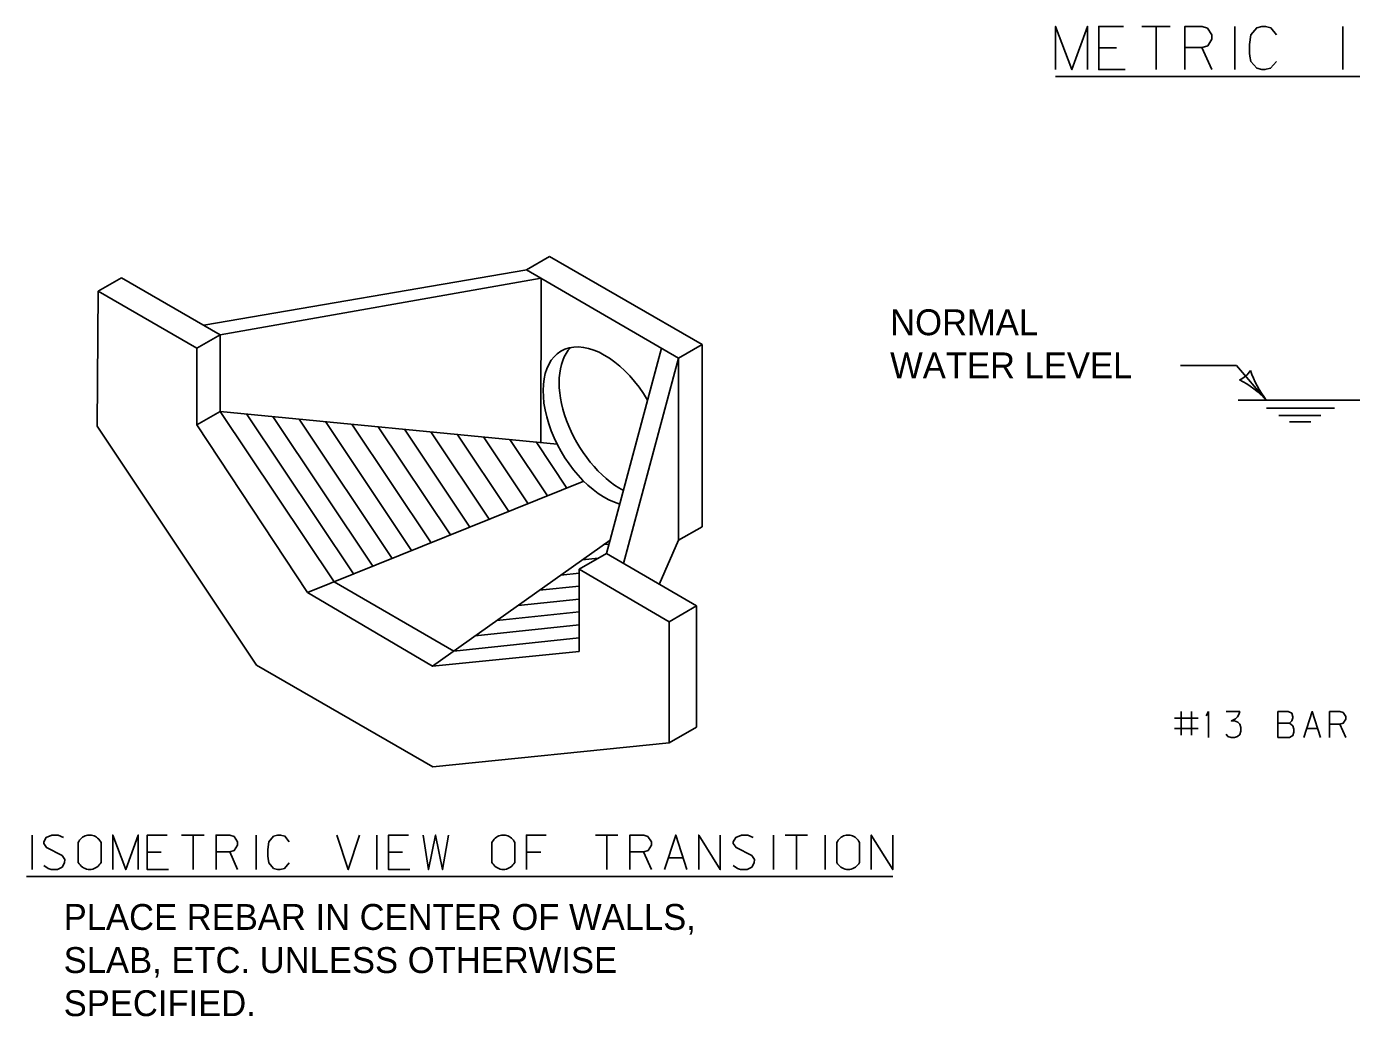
# Model space of a CAD drawing. Extents: x 49991.4 to 50043, y 49987.6 to 50011.4.
# Drawn here: x 50035.187 to 50038.261, y 49996.433 to 49998.729 of the extents above; entities that cross this region are included whole.
import ezdxf

# ---------------------------------------------------------------- set-up
doc = ezdxf.new("R2010")
doc.units = 0
for name, color, linetype in [('Level 1', 7, 'Continuous'), ('Level 2', 7, 'Continuous'), ('Level 3', 7, 'Continuous')]:
    doc.layers.add(name, color=color, linetype=linetype)

msp = doc.modelspace()

# ---------------------------------------------------------------- linework, layer by layer
at = {"layer": 'Level 1'}
for p, q in [((50036.4004, 49998.1956), (50036.3472, 49998.1648)), ((50036.7543, 49997.9911), (50036.4004, 49998.1956)), ((50036.3473, 49998.1648), (50035.5983, 49998.0359)), ((50036.3472, 49998.1648), (50036.6998, 49997.9596)), ((50035.3528, 49998.1146), (50035.4073, 49998.1461)), ((50035.6363, 49998.0139), (50035.4073, 49998.1461)), ((50036.3811, 49998.1451), (50035.6363, 49998.0139)), ((50036.3811, 49998.1451), (50036.3798, 49997.7642)), ((50035.3528, 49998.1146), (50035.3507, 49997.8017)), ((50035.5818, 49997.9824), (50035.3528, 49998.1146)), ((50035.5818, 49997.9824), (50035.6363, 49998.0139)), ((50035.6363, 49998.0139), (50035.6363, 49997.8361)), ((50035.5818, 49997.9824), (50035.5818, 49997.8046)), ((50036.5323, 49997.5066), (50036.6601, 49997.9827)), ((50036.6998, 49997.9596), (50036.7543, 49997.9911)), ((50036.7543, 49997.9911), (50036.7543, 49997.5687)), ((50036.5722, 49997.4834), (50036.6998, 49997.9596)), ((50036.6998, 49997.5372), (50036.6998, 49997.9596)), ((50037.9983, 49997.8625), (50038.3287, 49997.8625)), ((50035.5818, 49997.8046), (50035.6363, 49997.8361)), ((50035.6363, 49997.8361), (50035.9002, 49997.4411)), ((50035.6363, 49997.8361), (50036.4179, 49997.7605)), ((50035.6974, 49997.8302), (50035.9452, 49997.4592)), ((50035.7585, 49997.8243), (50035.9903, 49997.4773)), ((50035.8195, 49997.8184), (50036.0353, 49997.4954)), ((50038.0635, 49997.8436), (50038.2214, 49997.8436)), ((50038.0927, 49997.8265), (50038.1897, 49997.8265)), ((50035.3507, 49997.8017), (50035.7207, 49997.248)), ((50035.5818, 49997.8046), (50035.8388, 49997.4164)), ((50035.8806, 49997.8125), (50036.0803, 49997.5135)), ((50035.9416, 49997.8066), (50036.1253, 49997.5316)), ((50036.0027, 49997.8007), (50036.1704, 49997.5497)), ((50036.0638, 49997.7948), (50036.2154, 49997.5678)), ((50036.1248, 49997.7889), (50036.2604, 49997.5859)), ((50036.1859, 49997.783), (50036.3055, 49997.604)), ((50038.1176, 49997.8123), (50038.1671, 49997.8123)), ((50036.2469, 49997.7771), (50036.3505, 49997.622)), ((50036.308, 49997.7712), (50036.3955, 49997.6401)), ((50036.3691, 49997.7652), (50036.4405, 49997.6582)), ((50035.8388, 49997.4164), (50036.48, 49997.6741)), ((50036.7543, 49997.5687), (50036.6998, 49997.5372)), ((50036.1288, 49997.2452), (50036.5407, 49997.5378)), ((50036.6998, 49997.5372), (50036.655, 49997.4351)), ((50036.5323, 49997.5066), (50036.4693, 49997.4702)), ((50036.5382, 49997.5285), (50036.5257, 49997.5271)), ((50036.5323, 49997.5066), (50036.7411, 49997.3849)), ((50036.5137, 49997.4958), (50036.4761, 49997.4919)), ((50036.4693, 49997.4611), (50036.4265, 49997.4567)), ((50036.4693, 49997.4702), (50036.4693, 49997.2791)), ((50036.4693, 49997.4702), (50036.6775, 49997.3483)), ((50035.8388, 49997.4164), (50036.1288, 49997.2452)), ((50035.9002, 49997.4411), (50036.1784, 49997.2805)), ((50036.4693, 49997.4311), (50036.3769, 49997.4214)), ((50036.4693, 49997.401), (50036.3273, 49997.3862)), ((50036.7411, 49997.3849), (50036.6775, 49997.3483)), ((50036.7411, 49997.3849), (50036.7411, 49997.1042)), ((50036.4693, 49997.371), (50036.2777, 49997.3509)), ((50036.4693, 49997.3409), (50036.228, 49997.3157)), ((50036.6775, 49997.3483), (50036.6775, 49997.0674)), ((50036.4693, 49997.3108), (50036.1784, 49997.2805)), ((50036.4693, 49997.2791), (50036.1288, 49997.2452)), ((50036.1295, 49997.012), (50035.7207, 49997.248)), ((50036.7411, 49997.1042), (50036.6775, 49997.0674)), ((50036.6775, 49997.0674), (50036.1295, 49997.012))]:
    msp.add_line(p, q, dxfattribs=at)
for centre, start_param, end_param in [((50036.5283, 49997.8013), 4.726836, 8.88612), ((50036.5654, 49997.8211), 0.161802, 2.399384)]:
    msp.add_ellipse(centre, major_axis=(-0.101, 0.1749), ratio=0.57735, start_param=start_param, end_param=end_param, dxfattribs=at)
at = {"layer": 'Level 2'}
for p, q in [((50037.7746, 49998.7287), (50037.84, 49998.7287)), ((50037.8077, 49998.7287), (50037.8077, 49998.6287)), ((50037.9907, 49998.6287), (50037.9907, 49998.7287)), ((50038.2407, 49998.6287), (50038.2407, 49998.7287)), ((50037.7155, 49998.6791), (50037.6746, 49998.6791)), ((50037.9368, 49998.6287), (50037.914, 49998.6798)), ((50037.5746, 49998.6127), (50040.7368, 49998.6127)), ((50037.8656, 49997.1402), (50037.8656, 49997.0852)), ((50037.8899, 49997.1402), (50037.8899, 49997.0852)), ((50037.9296, 49997.1402), (50037.9237, 49997.1298)), ((50037.9296, 49997.1402), (50037.9296, 49997.0802)), ((50037.8502, 49997.1249), (50037.9053, 49997.1249)), ((50038.2476, 49997.0802), (50038.2339, 49997.1109)), ((50037.8502, 49997.1005), (50037.9053, 49997.1005)), ((50038.1569, 49997.1005), (50038.1828, 49997.1005)), ((50035.1996, 49996.7738), (50035.1996, 49996.8538)), ((50035.3067, 49996.8361), (50035.3067, 49996.7901)), ((50035.33, 49996.8538), (50035.3363, 49996.8538)), ((50035.3596, 49996.8361), (50035.3596, 49996.7901)), ((50035.5467, 49996.8538), (50035.599, 49996.8538)), ((50035.5731, 49996.8538), (50035.5731, 49996.7738)), ((50035.7196, 49996.7738), (50035.7196, 49996.8538)), ((50035.9996, 49996.7738), (50035.9996, 49996.8538)), ((50036.2667, 49996.8361), (50036.2667, 49996.7901)), ((50036.29, 49996.8538), (50036.2963, 49996.8538)), ((50036.3196, 49996.8361), (50036.3196, 49996.7901)), ((50036.5067, 49996.8538), (50036.559, 49996.8538)), ((50036.5331, 49996.8538), (50036.5331, 49996.7738)), ((50036.9196, 49996.7738), (50036.9196, 49996.8538)), ((50036.9467, 49996.8538), (50036.999, 49996.8538)), ((50036.9731, 49996.8538), (50036.9731, 49996.7738)), ((50037.0396, 49996.7738), (50037.0396, 49996.8538)), ((50037.0667, 49996.8361), (50037.0667, 49996.7901)), ((50037.09, 49996.8538), (50037.0963, 49996.8538)), ((50037.1196, 49996.8361), (50037.1196, 49996.7901)), ((50035.4994, 49996.8141), (50035.4667, 49996.8141)), ((50035.6765, 49996.7738), (50035.6582, 49996.8147)), ((50036.0594, 49996.8141), (50036.0267, 49996.8141)), ((50036.3473, 49996.8141), (50036.3801, 49996.8141)), ((50036.6365, 49996.7738), (50036.6182, 49996.8147)), ((50036.6755, 49996.8009), (50036.7102, 49996.8009)), ((50035.33, 49996.7738), (50035.3363, 49996.7738)), ((50036.29, 49996.7738), (50036.2963, 49996.7738)), ((50037.09, 49996.7738), (50037.0963, 49996.7738)), ((50035.1867, 49996.7578), (50037.1965, 49996.7578))]:
    msp.add_line(p, q, dxfattribs=at)
for points in [[(50037.5746, 49998.6287), (50037.5746, 49998.7287), (50037.6124, 49998.6287), (50037.6486, 49998.7287), (50037.6486, 49998.6287)], [(50037.7321, 49998.7287), (50037.6746, 49998.7287), (50037.6746, 49998.6287), (50037.736, 49998.6287)], [(50037.8746, 49998.6287), (50037.8746, 49998.7287), (50037.9148, 49998.7287), (50037.9266, 49998.7247), (50037.9368, 49998.709), (50037.9368, 49998.6995), (50037.9274, 49998.6838), (50037.9148, 49998.6798), (50037.8746, 49998.6798)], [(50038.0868, 49998.709), (50038.0742, 49998.7255), (50038.0616, 49998.7287), (50038.053, 49998.7287), (50038.0411, 49998.7255), (50038.0278, 49998.709), (50038.0246, 49998.6869), (50038.0246, 49998.6751), (50038.0246, 49998.6672), (50038.0254, 49998.6602), (50038.0278, 49998.6476), (50038.0411, 49998.6318), (50038.053, 49998.6287), (50038.06, 49998.6287), (50038.0734, 49998.6318), (50038.0868, 49998.6476)], [(50037.9702, 49997.1402), (50038.0019, 49997.1402), (50038, 49997.1331), (50037.9967, 49997.1279), (50037.992, 49997.1232), (50037.9825, 49997.1185), (50037.9896, 49997.1185), (50037.9972, 49997.1152), (50038.0019, 49997.1105), (50038.0043, 49997.1029), (50038.0043, 49997.0949), (50038.0019, 49997.0868), (50037.9967, 49997.0821), (50037.9896, 49997.0802), (50037.9816, 49997.0802), (50037.9745, 49997.0821), (50037.9702, 49997.0873)], [(50038.1172, 49997.1128), (50038.1224, 49997.1185), (50038.1247, 49997.1256), (50038.1247, 49997.1279), (50038.1224, 49997.136), (50038.1143, 49997.1402), (50038.0902, 49997.1402), (50038.0902, 49997.0802), (50038.1172, 49997.0802), (50038.1247, 49997.0845), (50038.1276, 49997.0925), (50038.1276, 49997.0996), (50038.1247, 49997.1067), (50038.1172, 49997.1128), (50038.0902, 49997.1128)], [(50038.1502, 49997.0802), (50038.1701, 49997.1402), (50038.1895, 49997.0802)], [(50038.2102, 49997.0802), (50038.2102, 49997.1402), (50038.2343, 49997.1402), (50038.2414, 49997.1379), (50038.2476, 49997.1284), (50038.2476, 49997.1227), (50038.2419, 49997.1133), (50038.2343, 49997.1109), (50038.2102, 49997.1109)], [(50035.2727, 49996.8481), (50035.2601, 49996.8538), (50035.2456, 49996.8538), (50035.2324, 49996.8481), (50035.2267, 49996.838), (50035.2267, 49996.8342), (50035.233, 49996.8248), (50035.2695, 49996.8059), (50035.2758, 49996.7971), (50035.2752, 49996.7895), (50035.2695, 49996.7794), (50035.2588, 49996.7738), (50035.2437, 49996.7738), (50035.2368, 49996.7763), (50035.2267, 49996.7832)], [(50035.3067, 49996.8361), (50035.3082, 49996.839), (50035.31, 49996.8417), (50035.3121, 49996.8442), (50035.3145, 49996.8465), (50035.317, 49996.8485), (50035.3198, 49996.8502), (50035.3227, 49996.8517), (50035.3258, 49996.8528), (50035.3289, 49996.8536), (50035.33, 49996.8538)], [(50035.3596, 49996.8361), (50035.3581, 49996.839), (50035.3563, 49996.8417), (50035.3542, 49996.8442), (50035.3518, 49996.8465), (50035.3493, 49996.8485), (50035.3465, 49996.8502), (50035.3436, 49996.8517), (50035.3405, 49996.8528), (50035.3374, 49996.8536), (50035.3363, 49996.8538)], [(50035.3867, 49996.7738), (50035.3867, 49996.8538), (50035.4169, 49996.7738), (50035.4459, 49996.8538), (50035.4459, 49996.7738)], [(50035.5127, 49996.8538), (50035.4667, 49996.8538), (50035.4667, 49996.7738), (50035.5158, 49996.7738)], [(50035.6267, 49996.7738), (50035.6267, 49996.8538), (50035.6588, 49996.8538), (50035.6683, 49996.8506), (50035.6765, 49996.838), (50035.6765, 49996.8305), (50035.6689, 49996.8179), (50035.6588, 49996.8147), (50035.6267, 49996.8147)], [(50035.7965, 49996.838), (50035.7864, 49996.8513), (50035.7763, 49996.8538), (50035.7694, 49996.8538), (50035.7599, 49996.8513), (50035.7492, 49996.838), (50035.7467, 49996.8204), (50035.7467, 49996.8109), (50035.7467, 49996.8046), (50035.7473, 49996.799), (50035.7492, 49996.7889), (50035.7599, 49996.7763), (50035.7694, 49996.7738), (50035.775, 49996.7738), (50035.7857, 49996.7763), (50035.7965, 49996.7889)], [(50035.9067, 49996.8538), (50035.9331, 49996.7738), (50035.959, 49996.8538)], [(50036.0727, 49996.8538), (50036.0267, 49996.8538), (50036.0267, 49996.7738), (50036.0758, 49996.7738)], [(50036.1067, 49996.8538), (50036.1193, 49996.7738), (50036.1357, 49996.8538), (50036.152, 49996.7738), (50036.1659, 49996.8538)], [(50036.2667, 49996.8361), (50036.2682, 49996.839), (50036.27, 49996.8417), (50036.2721, 49996.8442), (50036.2745, 49996.8465), (50036.277, 49996.8485), (50036.2798, 49996.8502), (50036.2827, 49996.8517), (50036.2858, 49996.8528), (50036.2889, 49996.8536), (50036.29, 49996.8538)], [(50036.3196, 49996.8361), (50036.3181, 49996.839), (50036.3163, 49996.8417), (50036.3142, 49996.8442), (50036.3118, 49996.8465), (50036.3093, 49996.8485), (50036.3065, 49996.8502), (50036.3036, 49996.8517), (50036.3005, 49996.8528), (50036.2974, 49996.8536), (50036.2963, 49996.8538)], [(50036.3927, 49996.8538), (50036.3467, 49996.8538), (50036.3467, 49996.7738)], [(50036.5867, 49996.7738), (50036.5867, 49996.8538), (50036.6188, 49996.8538), (50036.6283, 49996.8506), (50036.6365, 49996.838), (50036.6365, 49996.8305), (50036.6289, 49996.8179), (50036.6188, 49996.8147), (50036.5867, 49996.8147)], [(50036.6667, 49996.7738), (50036.6931, 49996.8538), (50036.719, 49996.7738)], [(50036.7467, 49996.7738), (50036.7467, 49996.8538), (50036.7965, 49996.7738), (50036.7965, 49996.8538)], [(50036.8727, 49996.8481), (50036.8601, 49996.8538), (50036.8456, 49996.8538), (50036.8324, 49996.8481), (50036.8267, 49996.838), (50036.8267, 49996.8342), (50036.833, 49996.8248), (50036.8695, 49996.8059), (50036.8758, 49996.7971), (50036.8752, 49996.7895), (50036.8695, 49996.7794), (50036.8588, 49996.7738), (50036.8437, 49996.7738), (50036.8368, 49996.7763), (50036.8267, 49996.7832)], [(50037.0667, 49996.8361), (50037.0682, 49996.839), (50037.07, 49996.8417), (50037.0721, 49996.8442), (50037.0745, 49996.8465), (50037.077, 49996.8485), (50037.0798, 49996.8502), (50037.0827, 49996.8517), (50037.0858, 49996.8528), (50037.0889, 49996.8536), (50037.09, 49996.8538)], [(50037.1196, 49996.8361), (50037.1181, 49996.839), (50037.1163, 49996.8417), (50037.1142, 49996.8442), (50037.1118, 49996.8465), (50037.1093, 49996.8485), (50037.1065, 49996.8502), (50037.1036, 49996.8517), (50037.1005, 49996.8528), (50037.0974, 49996.8536), (50037.0963, 49996.8538)], [(50037.1467, 49996.7738), (50037.1467, 49996.8538), (50037.1965, 49996.7738), (50037.1965, 49996.8538)], [(50035.3067, 49996.7901), (50035.3087, 49996.7871), (50035.3109, 49996.7844), (50035.3135, 49996.7818), (50035.3163, 49996.7796), (50035.3193, 49996.7777), (50035.3226, 49996.7761), (50035.3259, 49996.7748), (50035.3294, 49996.7739), (50035.33, 49996.7738)], [(50035.3596, 49996.7901), (50035.3576, 49996.7871), (50035.3553, 49996.7844), (50035.3528, 49996.7818), (50035.35, 49996.7796), (50035.3469, 49996.7777), (50035.3437, 49996.7761), (50035.3404, 49996.7748), (50035.3369, 49996.7739), (50035.3363, 49996.7738)], [(50036.2667, 49996.7901), (50036.2687, 49996.7871), (50036.2709, 49996.7844), (50036.2735, 49996.7818), (50036.2763, 49996.7796), (50036.2793, 49996.7777), (50036.2826, 49996.7761), (50036.2859, 49996.7748), (50036.2894, 49996.7739), (50036.29, 49996.7738)], [(50036.3196, 49996.7901), (50036.3176, 49996.7871), (50036.3153, 49996.7844), (50036.3128, 49996.7818), (50036.31, 49996.7796), (50036.3069, 49996.7777), (50036.3037, 49996.7761), (50036.3004, 49996.7748), (50036.2969, 49996.7739), (50036.2963, 49996.7738)], [(50037.0667, 49996.7901), (50037.0687, 49996.7871), (50037.0709, 49996.7844), (50037.0735, 49996.7818), (50037.0763, 49996.7796), (50037.0793, 49996.7777), (50037.0826, 49996.7761), (50037.0859, 49996.7748), (50037.0894, 49996.7739), (50037.09, 49996.7738)], [(50037.1196, 49996.7901), (50037.1176, 49996.7871), (50037.1153, 49996.7844), (50037.1128, 49996.7818), (50037.11, 49996.7796), (50037.1069, 49996.7777), (50037.1037, 49996.7761), (50037.1004, 49996.7748), (50037.0969, 49996.7739), (50037.0963, 49996.7738)]]:
    msp.add_lwpolyline(points, dxfattribs=at)
at = {"layer": 'Level 3'}
for p, q in [((50037.9945, 49997.9428), (50037.8646, 49997.9428)), ((50038.0634, 49997.8625), (50037.9945, 49997.9428))]:
    msp.add_line(p, q, dxfattribs=at)
for centre, radius, start, end in [((50037.98, 49997.9599), 0.0548, 292.7196, 328.442), ((50037.9006, 49997.7111), 0.2223, 42.9413, 63.1248), ((50038.2476, 49998.0052), 0.233, 198.5036, 217.7535)]:
    msp.add_arc(centre, radius, start, end, dxfattribs=at)

# ---------------------------------------------------------------- texts
at = {"layer": 'Level 2'}
for s, p in [('NORMAL', (50037.1906, 49998.0128)), ('WATER LEVEL', (50037.1906, 49997.9128)), ('PLACE REBAR IN CENTER OF WALLS,', (50035.273, 49996.6338)), ('SLAB, ETC. UNLESS OTHERWISE', (50035.273, 49996.5338)), ('SPECIFIED.', (50035.273, 49996.4338))]:
    msp.add_text(s, height=0.06, dxfattribs=at).set_placement(p)

doc.saveas('drawing.dxf')
